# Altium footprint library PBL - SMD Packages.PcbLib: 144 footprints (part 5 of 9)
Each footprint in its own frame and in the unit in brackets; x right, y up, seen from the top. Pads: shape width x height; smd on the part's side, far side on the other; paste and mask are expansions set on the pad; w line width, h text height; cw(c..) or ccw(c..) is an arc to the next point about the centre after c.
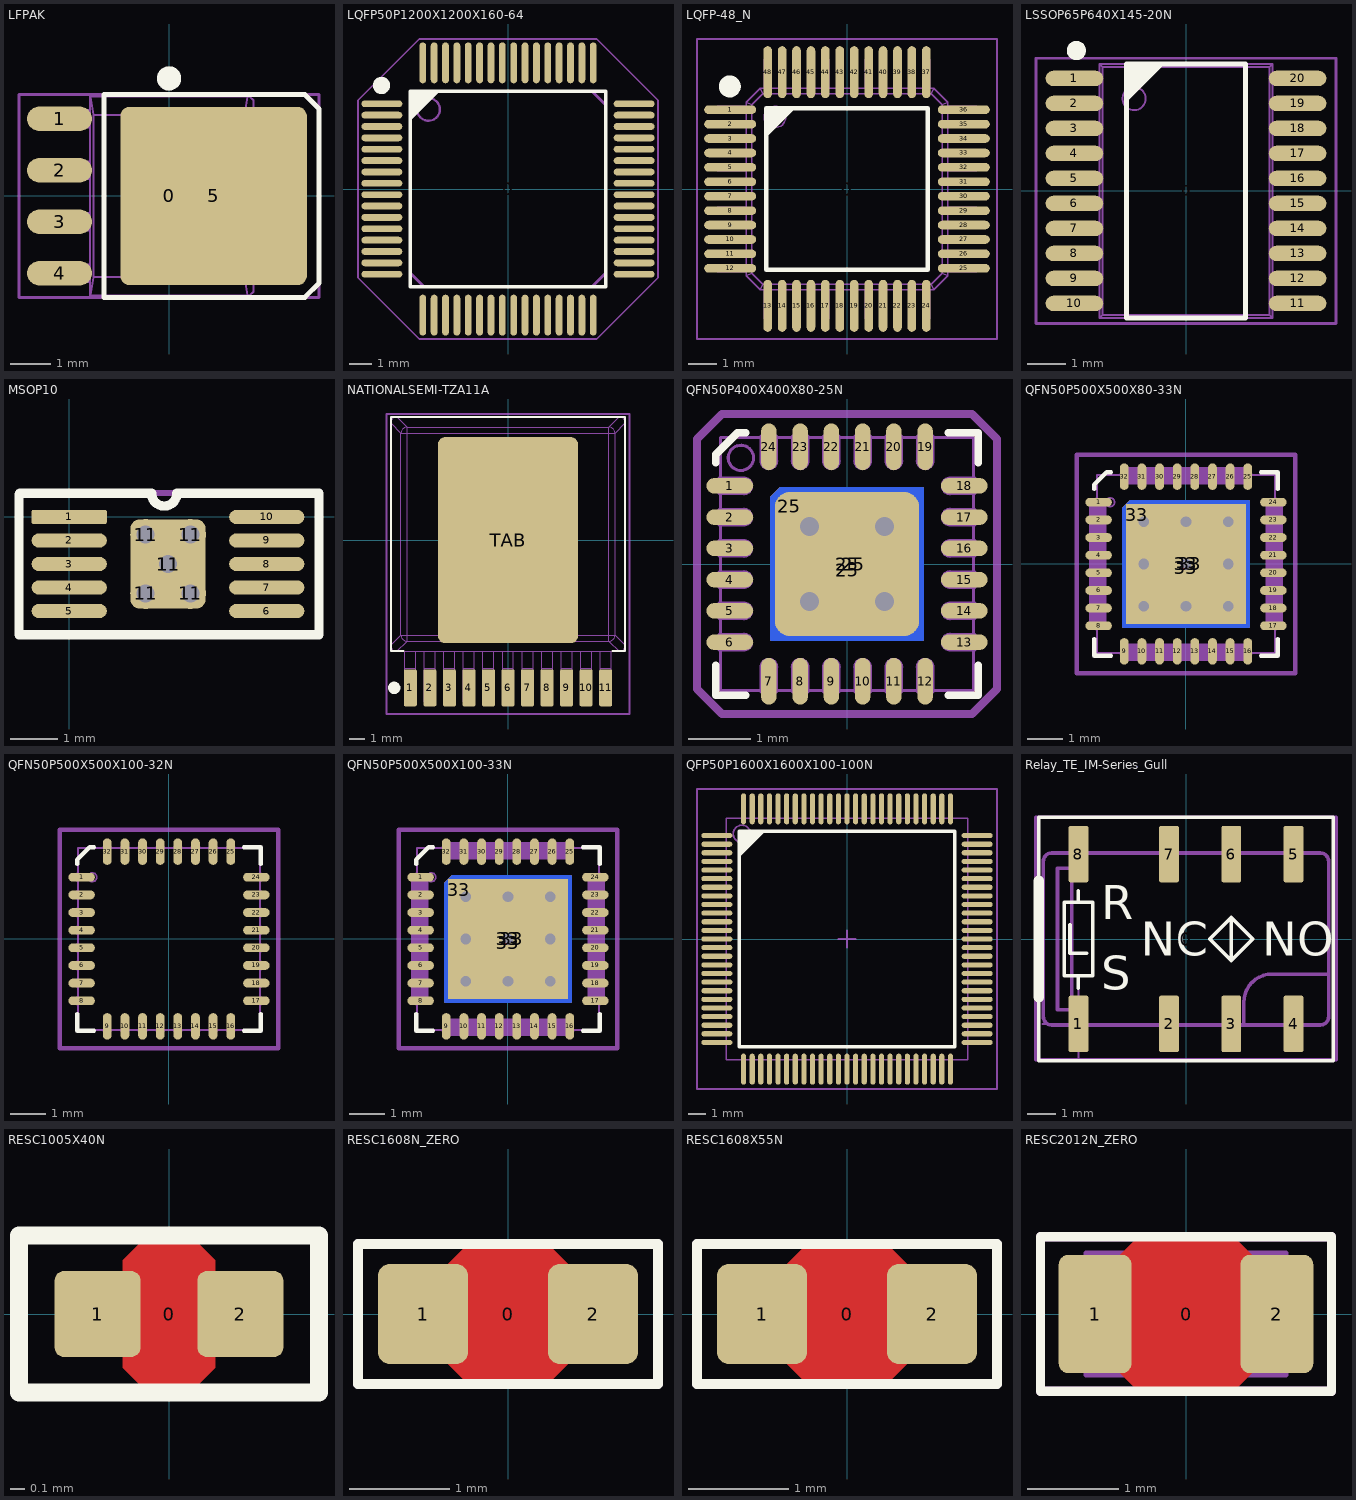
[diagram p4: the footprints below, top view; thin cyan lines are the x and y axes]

## LFPAK [mm] "Renesas LFPAK, a variant of SOIC-8; IPC Medium Density"
height 1.1
pads (6):
  round 1 on Mech15: 0(0,0)
  oval 1.6x0.6 smd: 1(-2.7,1.905) 2(-2.7,0.635) 3(-2.7,-0.635) 4(-2.7,-1.905)
  rrect10% 4.6x4.4 smd paste-0.8: 5(1.1,0)
Top Overlay:
  circle w0.3: c0,2.9 r0.15
  lines w0.127: -1.6,-2.5 -1.6,2.5 3.35,2.5 3.7,2.15 3.7,-2.15 3.35,-2.5 -1.6,-2.5
13 - 3D Top Side:
  circle w0.05: c0,1.5 r0.338
  lines w0.05: -2.631,-2.115 -2.631,-1.695 ; -2.631,-0.845 -2.631,-0.425 ; -2.631,0.425 -2.631,0.845 ; -2.631,1.695 -2.631,2.115 ; -2.543,-2.115 -2.543,-1.695 ; -2.543,-0.845 -2.543,-0.425 ; -2.543,0.425 -2.543,0.845 ; -2.543,1.695 -2.543,2.115 ; -2.506,-2.115 -2.506,-1.695 ; -2.506,-0.845 -2.506,-0.425 ; -2.506,0.425 -2.506,0.845 ; -2.506,1.695 -2.506,2.115 ; -2.217,-2.115 -2.217,-1.695 ; -2.217,-0.845 -2.217,-0.425 ; -2.217,0.425 -2.217,0.845 ; -2.217,1.695 -2.217,2.115 ; -1.95,-2.115 -3,-2.115 -3,-1.695 -1.95,-1.695 ; -1.95,-0.845 -3,-0.845 -3,-0.425 -1.95,-0.425 ; -1.95,0.425 -3,0.425 -3,0.845 -1.95,0.845 ; -1.95,1.695 -3,1.695 -3,2.115 -1.95,2.115 ; -1.937,-2.45 -1.858,-2.003 ; -1.937,2.45 -1.858,2.003 ; 1.937,-2.45 1.858,-2.003 ; 1.937,2.45 1.858,2.003 ; 2.085,-1.4 2.085,-2.358 1.993,-2.45 -1.95,-2.45 -1.95,2.45 1.993,2.45 2.085,2.358 2.085,1.4 ; 2.085,-0.6 2.085,0.6 ; -1.858,-2.003 -1.858,2.003 ; -1.858,-2.003 1.858,-2.003 ; -1.858,2.003 1.858,2.003 ; 1.858,-2.003 1.858,2.003 ; 2.028,-1.4 2.3,-1.4 2.3,-2.1 2.55,-2.1 3,-1.65 3,1.65 2.55,2.1 2.3,2.1 2.3,1.4 2.028,1.4 2.028,0.6 2.1,0.6 2.1,-0.6 2.028,-0.6 2.028,-1.4
15 - Top Courtyards:
  lines w0.076: -3.7,-2.5 -3.7,2.5 3.7,2.5 3.7,-2.5 -3.7,-2.5
3D body "LFPAK.STEP": height 1.1, standoff 0, extent -3,-2.45 3,2.45

## LQFP50P1200X1200X160-64 [mm] "Thin Quad Flat Pack, 64 pins, 0.5mm pitch, 12mm lead span, body 10x10mm, 0.1mm body height, max tolerances, IPC Medium Density"
height 1.6
pads (65):
  round 1 on Mech15: 0(0,0)
  oval 1.8x0.3 smd: 1(-5.55,3.75) 2(-5.55,3.25) 3(-5.55,2.75) 4(-5.55,2.25) 5(-5.55,1.75) 6(-5.55,1.25) 7(-5.55,0.75) 8(-5.55,0.25) 9(-5.55,-0.25) 10(-5.55,-0.75) 11(-5.55,-1.25) 12(-5.55,-1.75) 13(-5.55,-2.25) 14(-5.55,-2.75) 15(-5.55,-3.25) 16(-5.55,-3.75) 33(5.55,-3.75) 34(5.55,-3.25) 35(5.55,-2.75) 36(5.55,-2.25) 37(5.55,-1.75) 38(5.55,-1.25) 39(5.55,-0.75) 40(5.55,-0.25) 41(5.55,0.25) 42(5.55,0.75) 43(5.55,1.25) 44(5.55,1.75) 45(5.55,2.25) 46(5.55,2.75) 47(5.55,3.25) 48(5.55,3.75)
  oval 0.3x1.8 smd: 17(-3.75,-5.55) 18(-3.25,-5.55) 19(-2.75,-5.55) 20(-2.25,-5.55) 21(-1.75,-5.55) 22(-1.25,-5.55) 23(-0.75,-5.55) 24(-0.25,-5.55) 25(0.25,-5.55) 26(0.75,-5.55) 27(1.25,-5.55) 28(1.75,-5.55) 29(2.25,-5.55) 30(2.75,-5.55) 31(3.25,-5.55) 32(3.75,-5.55) 49(3.75,5.55) 50(3.25,5.55) 51(2.75,5.55) 52(2.25,5.55) 53(1.75,5.55) 54(1.25,5.55) 55(0.75,5.55) 56(0.25,5.55) 57(-0.25,5.55) 58(-0.75,5.55) 59(-1.25,5.55) 60(-1.75,5.55) 61(-2.25,5.55) 62(-2.75,5.55) 63(-3.25,5.55) 64(-3.75,5.55)
Top Overlay:
  circle w0.381: c-5.564,4.556 r0.191
  region: -4.294,4.294 -3.006,4.294 -4.294,3.006
  lines w0.152: -4.3,-4.3 4.3,-4.3 4.3,4.3 -4.3,4.3 -4.3,-4.3
13 - 3D Top Side:
  circle w0.1: c-3.5,3.5 r0.5
  lines w0.127: -4.3,-3.7 -3.7,-4.3 3.7,-4.3 4.3,-3.7 4.3,3.7 3.7,4.3 -3.7,4.3 -4.3,3.7 -4.3,-3.7
15 - Top Courtyards:
  lines w0.076: -6.6,-3.9 -3.9,-6.6 3.9,-6.6 6.6,-3.9 6.6,3.9 3.9,6.6 -3.9,6.6 -6.6,3.9 -6.6,-3.9
3D body "LQFP50P1200X1200X160-64.STEP": height 1.59, standoff -0.01, extent -6.1,-6.1 6.1,6.1

## LQFP-48_N [mm] "Thin QFP, 48-Leads, Body 7x7mm, Pitch 0.5mm, IPC Medium Density"
height 1.6
pads (49):
  round 1 on Mech15: 0(0,0)
  oval 1.8x0.3 smd: 1(-4.05,2.75) 2(-4.05,2.25) 3(-4.05,1.75) 4(-4.05,1.25) 5(-4.05,0.75) 6(-4.05,0.25) 7(-4.05,-0.25) 8(-4.05,-0.75) 9(-4.05,-1.25) 10(-4.05,-1.75) 11(-4.05,-2.25) 12(-4.05,-2.75) 25(4.05,-2.75) 26(4.05,-2.25) 27(4.05,-1.75) 28(4.05,-1.25) 29(4.05,-0.75) 30(4.05,-0.25) 31(4.05,0.25) 32(4.05,0.75) 33(4.05,1.25) 34(4.05,1.75) 35(4.05,2.25) 36(4.05,2.75)
  oval 0.3x1.8 smd: 13(-2.75,-4.05) 14(-2.25,-4.05) 15(-1.75,-4.05) 16(-1.25,-4.05) 17(-0.75,-4.05) 18(-0.25,-4.05) 19(0.25,-4.05) 20(0.75,-4.05) 21(1.25,-4.05) 22(1.75,-4.05) 23(2.25,-4.05) 24(2.75,-4.05) 37(2.75,4.05) 38(2.25,4.05) 39(1.75,4.05) 40(1.25,4.05) 41(0.75,4.05) 42(0.25,4.05) 43(-0.25,4.05) 44(-0.75,4.05) 45(-1.25,4.05) 46(-1.75,4.05) 47(-2.25,4.05) 48(-2.75,4.05)
Top Overlay:
  circle w0.381: c-4.064,3.556 r0.191
  region: -2.794,2.794 -1.794,2.794 -2.794,1.794
  lines w0.152: -2.794,-2.794 -2.794,2.794 2.794,2.794 2.794,-2.794 -2.794,-2.794
13 - 3D Top Side:
  drawing of 361 lines, arcs and shapes, not listed
15 - Top Courtyards:
  lines w0.076: -5.2,-5.2 -5.2,5.2 5.2,5.2 5.2,-5.2 -5.2,-5.2
3D body "LQFP-48.STEP": height 1.59, standoff -0.01, extent -4.5,-4.5 4.5,4.5

## LSSOP65P640X145-20N [mm] "LSSOP, 20-Leads, Body 6.6x4.5mm (max), Pitch 0.65mm, IPC Medium Density"
height 1.45
pads (21):
  round 0.508 on Mech15 mask+0.127: 0(0,0)
  oval 1.5x0.4 smd paste-1 mask+0.127: 1(-2.9,2.925) 2(-2.9,2.275) 3(-2.9,1.625) 4(-2.9,0.975) 5(-2.9,0.325) 6(-2.9,-0.325) 7(-2.9,-0.975) 8(-2.9,-1.625) 9(-2.9,-2.275) 10(-2.9,-2.925) 11(2.9,-2.925) 12(2.9,-2.275) 13(2.9,-1.625) 14(2.9,-0.975) 15(2.9,-0.325) 16(2.9,0.325) 17(2.9,0.975) 18(2.9,1.625) 19(2.9,2.275) 20(2.9,2.925)
Top Overlay:
  circle w0.25: c-2.85,3.65 r0.125
  region: -1.55,3.3 -0.55,3.3 -1.55,2.3
  lines w0.127: -1.55,-3.3 -1.55,3.3 1.55,3.3 1.55,-3.3 -1.55,-3.3
Top Paste:
  region: 3.5,-0.825 2.3,-0.825 2.3,-1.125 3.5,-1.125
  region: 3.5,-0.175 2.3,-0.175 2.3,-0.475 3.5,-0.475
  region: 3.5,0.475 2.3,0.475 2.3,0.175 3.5,0.175
  region: 3.5,1.125 2.3,1.125 2.3,0.825 3.5,0.825
  region: 3.5,1.775 2.3,1.775 2.3,1.475 3.5,1.475
  region: 3.5,2.425 2.3,2.425 2.3,2.125 3.5,2.125
  region: 3.5,3.075 2.3,3.075 2.3,2.775 3.5,2.775
  rectangle: -3.5,2.775 -2.3,3.075
  rectangle: -3.5,2.125 -2.3,2.425
  rectangle: -3.5,1.475 -2.3,1.775
  rectangle: -3.5,0.825 -2.3,1.125
  rectangle: -3.5,0.175 -2.3,0.475
  rectangle: -3.5,-0.475 -2.3,-0.175
  rectangle: -3.5,-1.125 -2.3,-0.825
  rectangle: -3.5,-3.075 -2.3,-2.775
  rectangle: -3.5,-2.425 -2.3,-2.125
  rectangle: -3.5,-1.775 -2.3,-1.475
  region: 3.5,-1.475 2.3,-1.475 2.3,-1.775 3.5,-1.775
  region: 3.5,-2.125 2.3,-2.125 2.3,-2.425 3.5,-2.425
  region: 3.5,-2.775 2.3,-2.775 2.3,-3.075 3.5,-3.075
13 - 3D Top Side:
  drawing of 153 lines, arcs and shapes, not listed
15 - Top Courtyards:
  lines w0.076: -3.9,-3.45 -3.9,3.45 3.9,3.45 3.9,-3.45 -3.9,-3.45
3D body "LSSOP65P640X145-20N.STEP": height 1.45, standoff 0, extent -3.3,-3.3 3.3,3.3

## MSOP10 [mm]
pads (16):
  rrect25% 1.6x0.3 smd mask+0.05: 1(0,0)
  oval 1.6x0.3 smd mask+0.05: 2(0,-0.5) 3(0,-1) 4(0,-1.5) 5(0,-2) 6(4.2,-2) 7(4.2,-1.5) 8(4.2,-1) 9(4.2,-0.5) 10(4.2,0)
  round 0.66 hole 0.381: 11(1.625,-1.625) 11(1.625,-0.375) 11(2.1,-1) 11(2.575,-1.625) 11(2.575,-0.375)
  rrect25% 1.6x1.9 smd: 11(2.1,-1)
Top Overlay:
  lines w0.2: 1.725,0.5 -1.049,0.5 -1.067,0.483 -1.067,-2.5 5.309,-2.5 5.309,0.5 2.3,0.5 ; 1.75,0.5 ccw(c2.019,0.5) 2.289,0.5
Top Solder:
  rectangle: 1.175,-2.075 3.025,0.075
15 - Top Courtyards:
  lines w0.127: -1.067,-2.489 -1.067,0.508 5.309,0.508 5.309,-2.489 -1.067,-2.489
3D body: height 0.15, standoff 0, extent -0.375,-2.125 4.6,0.125
3D body: height 1.1, standoff 0, extent 0.625,-2.5 3.625,0.525

## NATIONALSEMI-TZA11A [mm] "National Semi TZA11A package"
height 6
pads (12):
  rrect25% 0.85x2.4 smd: 1(-6.35,-9.6) 2(-5.08,-9.6) 3(-3.81,-9.6) 4(-2.54,-9.6) 5(-1.27,-9.6) 6(0,-9.6) 7(1.27,-9.6) 8(2.54,-9.6) 9(3.81,-9.6) 10(5.08,-9.6) 11(6.35,-9.6)
  rrect10% 9.1x13.4 smd: TAB(0,0)
Top Overlay:
  circle w0.4: c-7.4,-9.6 r0.2
  lines w0.127: -6.8,-7.2 -7.6,-7.2 -7.6,8 7.6,8 7.6,-7.2 6.8,-7.2
13 - 3D Top Side:
  lines w0.05: -6.705,-9.644 -5.995,-9.644 ; -6.705,-9.29 -5.995,-9.29 ; -6.705,-8.865 -5.995,-8.865 ; -6.705,-8.325 -5.995,-8.325 ; -6.705,-7.235 -6.705,-10.515 -5.995,-10.515 -5.995,-7.235 ; -5.435,-9.644 -4.725,-9.644 ; -5.435,-9.29 -4.725,-9.29 ; -5.435,-8.865 -4.725,-8.865 ; -5.435,-8.325 -4.725,-8.325 ; -5.435,-7.235 -5.435,-10.515 -4.725,-10.515 -4.725,-7.235 ; -4.165,-9.644 -3.455,-9.644 ; -4.165,-9.29 -3.455,-9.29 ; -4.165,-8.865 -3.455,-8.865 ; -4.165,-8.325 -3.455,-8.325 ; -4.165,-7.235 -4.165,-10.515 -3.455,-10.515 -3.455,-7.235 ; -2.895,-9.644 -2.185,-9.644 ; -2.895,-9.29 -2.185,-9.29 ; -2.895,-8.865 -2.185,-8.865 ; -2.895,-8.325 -2.185,-8.325 ; -2.895,-7.235 -2.895,-10.515 -2.185,-10.515 -2.185,-7.235 ; -1.625,-9.644 -0.915,-9.644 ; -1.625,-9.29 -0.915,-9.29 ; -1.625,-8.865 -0.915,-8.865 ; -1.625,-8.325 -0.915,-8.325 ; -1.625,-7.235 -1.625,-10.515 -0.915,-10.515 -0.915,-7.235 ; -0.355,-9.644 0.355,-9.644 ; -0.355,-9.29 0.355,-9.29 ; -0.355,-8.865 0.355,-8.865 ; -0.355,-8.325 0.355,-8.325 ; -0.355,-7.235 -0.355,-10.515 0.355,-10.515 0.355,-7.235 ; 0.915,-9.644 1.625,-9.644 ; 0.915,-9.29 1.625,-9.29 ; 0.915,-8.865 1.625,-8.865 ; 0.915,-8.325 1.625,-8.325 ; 0.915,-7.235 0.915,-10.515 1.625,-10.515 1.625,-7.235 ; 2.185,-9.644 2.895,-9.644 ; 2.185,-9.29 2.895,-9.29 ; 2.185,-8.865 2.895,-8.865 ; 2.185,-8.325 2.895,-8.325 ; 2.185,-7.235 2.185,-10.515 2.895,-10.515 2.895,-7.235 ; 3.455,-9.644 4.165,-9.644 ; 3.455,-9.29 4.165,-9.29 ; 3.455,-8.865 4.165,-8.865 ; 3.455,-8.325 4.165,-8.325 ; 3.455,-7.235 3.455,-10.515 4.165,-10.515 4.165,-7.235 ; 4.725,-9.644 5.435,-9.644 ; 4.725,-9.29 5.435,-9.29 ; 4.725,-8.865 5.435,-8.865 ; 4.725,-8.325 5.435,-8.325 ; 4.725,-7.235 4.725,-10.515 5.435,-10.515 5.435,-7.235 ; 5.995,-9.644 6.705,-9.644 ; 5.995,-9.29 6.705,-9.29 ; 5.995,-8.865 6.705,-8.865 ; 5.995,-8.325 6.705,-8.325 ; 5.995,-7.235 5.995,-10.515 6.705,-10.515 6.705,-7.235 ; -7.625,-6.839 ccw(c-7.225,-6.835) -7.229,-7.235 ; -7.625,-6.839 -7.625,-6.835 -7.625,7.615 -7.625,7.619 ; -7.625,-6.839 -6.958,-6.172 ; -7.625,7.619 cw(c-7.225,7.615) -7.229,8.015 ; -7.625,7.619 -6.958,6.952 ; -7.229,-7.235 -7.225,-7.235 7.225,-7.235 7.229,-7.235 ; -7.229,-7.235 -6.562,-6.568 ; -7.229,8.015 -7.225,8.015 7.225,8.015 7.229,8.015 ; -7.229,8.015 -6.562,7.348 ; -6.958,-6.172 ccw(c-6.553,-6.163) -6.562,-6.568 ; -6.958,-6.172 -6.958,6.952 ; -6.958,-6.172 6.958,-6.172 ; -6.958,6.952 cw(c-6.553,6.943) -6.562,7.348 ; -6.958,6.952 6.958,6.952 ; -6.562,-6.568 -6.562,7.348 ; -6.562,-6.568 6.562,-6.568 ; -6.562,7.348 6.562,7.348 ; 6.562,-6.568 ccw(c6.553,-6.163) 6.958,-6.172 ; 6.562,-6.568 7.229,-7.235 ; 6.562,-6.568 6.562,7.348 ; 6.562,7.348 cw(c6.553,6.943) 6.958,6.952 ; 6.562,7.348 7.229,8.015 ; 6.958,-6.172 7.625,-6.839 ; 6.958,-6.172 6.958,6.952 ; 6.958,6.952 7.625,7.619 ; 7.229,-7.235 ccw(c7.225,-6.835) 7.625,-6.839 ; 7.229,8.015 cw(c7.225,7.615) 7.625,7.619 ; 7.625,-6.839 7.625,-6.835 7.625,7.615 7.625,7.619
15 - Top Courtyards:
  lines w0.127: -7.9,-11.3 -7.9,8.2 7.9,8.2 7.9,-11.3 -7.9,-11.3
3D body "NATIONALSEMI-TZA11A.STEP": height 6, standoff 0, extent -7.625,-10.515 7.625,8.015

## QFN50P400X400X80-25N [mm] "QFN, 24-Leads with exposed die pad, Body 4.05x4.05mm (max), Pitch 0.50mm, IPC Medium Density"
height 0.8
pads (28):
  oval 0.75x0.25 smd mask+0.075: 1(-1.875,1.25) 2(-1.875,0.75) 3(-1.875,0.25) 4(-1.875,-0.25) 5(-1.875,-0.75) 6(-1.875,-1.25) 13(1.875,-1.25) 14(1.875,-0.75) 15(1.875,-0.25) 16(1.875,0.25) 17(1.875,0.75) 18(1.875,1.25)
  oval 0.25x0.75 smd mask+0.075: 7(-1.25,-1.875) 8(-0.75,-1.875) 9(-0.25,-1.875) 10(0.25,-1.875) 11(0.75,-1.875) 12(1.25,-1.875) 19(1.25,1.875) 20(0.75,1.875) 21(0.25,1.875) 22(-0.25,1.875) 23(-0.75,1.875) 24(-1.25,1.875)
  oct 0.6x0.6 smd far side paste-1.7: 25(-0.925,0.925)
  rrect1% 2.45x2.25 smd far side paste-1.7: 25(0,-0.1)
  rrect20% 2.3x2.3 smd paste-1.7: 25(0,0)
  rrect1% 2.25x2.45 smd far side paste-1.7: 25(0.1,0)
via -0.6,-0.6 diameter 0.4 hole 0.3
via 0.6,-0.6 diameter 0.4 hole 0.3
via 0.6,0.6 diameter 0.4 hole 0.3
via -0.6,0.6 diameter 0.4 hole 0.3
Top Layer:
  region: 1.025,-1.225 1.225,-1.225 1.225,1.225 1.025,1.225
  region: 1.225,-1.225 1.225,-1.025 -1.225,-1.025 -1.225,-1.225
  region: -1.225,1.075 -1.075,1.225 1.225,1.225 1.225,1.075
  region: -1.075,1.225 -1.225,1.075 -1.225,-1.225 -1.075,-1.225
Top Overlay:
  lines w0.127: -2.1,-1.625 -2.1,-2.1 -1.625,-2.1 ; -2.1,1.625 -2.1,1.75 -1.75,2.1 -1.625,2.1 ; 1.625,-2.1 2.1,-2.1 2.1,-1.625 ; 1.625,2.1 2.1,2.1 2.1,1.625
  text "." at -2.63,1.25 h0.05
Top Paste:
  region: -1.1,-0.3 -1.1,0.3 -1,0.4 -0.5,0.4 -0.4,0.5 -0.4,1 -0.3,1.1 0.3,1.1 0.4,1 0.4,0.5 0.5,0.4 1,0.4 1.1,0.3 1.1,-0.3 1,-0.4 0.5,-0.4 0.4,-0.5 0.4,-1 0.3,-1.1 -0.3,-1.1 -0.4,-1 -0.4,-0.5 -0.5,-0.4 -1,-0.4
Bottom Paste:
  region: 0.2,1 -0.2,1 -0.4,0.8 -0.4,0.5 -0.5,0.4 -0.8,0.4 -1,0.2 -1,-0.2 -0.8,-0.4 -0.5,-0.4 -0.4,-0.5 -0.4,-0.8 -0.2,-1 0.2,-1 0.4,-0.8 0.4,-0.5 0.5,-0.4 0.8,-0.4 1,-0.2 1,0.2 0.8,0.4 0.5,0.4 0.4,0.5 0.4,0.8
Top Solder:
  circle w0.4: c-0.6,-0.6 r0.4
  circle w0.4: c0.6,-0.6 r0.4
  circle w0.4: c0.6,0.6 r0.4
  circle w0.4: c-0.6,0.6 r0.4
  rectangle: -0.3,-1.225 0.3,1.2
  region: 1.225,-0.3 1.225,0.3 -1.2,0.3 -1.2,-0.3
13 - 3D Top Side:
  circle w0.05: c-1.698,1.698 r0.202
  lines w0.05: -2.025,-1.375 -2.025,-2.025 -1.375,-2.025 ; -2.025,-1.125 -2.025,-0.875 ; -2.025,-0.625 -2.025,-0.375 ; -2.025,-0.125 -2.025,0.125 ; -2.025,0.375 -2.025,0.625 ; -2.025,0.875 -2.025,1.125 ; -2.025,1.375 -2.025,2.025 -1.375,2.025 ; -1.125,-2.025 -0.875,-2.025 ; -1.125,2.025 -0.875,2.025 ; -0.625,-2.025 -0.375,-2.025 ; -0.625,2.025 -0.375,2.025 ; -0.125,-2.025 0.125,-2.025 ; -0.125,2.025 0.125,2.025 ; 0.375,-2.025 0.625,-2.025 ; 0.375,2.025 0.625,2.025 ; 0.875,-2.025 1.125,-2.025 ; 0.875,2.025 1.125,2.025 ; 1.375,-2.025 2.025,-2.025 2.025,-1.375 ; 1.375,2.025 2.025,2.025 2.025,1.375 ; 2.025,-1.125 2.025,-0.875 ; 2.025,-0.625 2.025,-0.375 ; 2.025,-0.125 2.025,0.125 ; 2.025,0.375 2.025,0.625 ; 2.025,0.875 2.025,1.125 ; -2.045,-1.375 -1.65,-1.375 ccw(c-1.65,-1.25) -1.65,-1.125 -2.045,-1.125 -2.045,-1.375 ; -2.045,-0.875 -1.65,-0.875 ccw(c-1.65,-0.75) -1.65,-0.625 -2.045,-0.625 -2.045,-0.875 ; -2.045,-0.375 -1.65,-0.375 ccw(c-1.65,-0.25) -1.65,-0.125 -2.045,-0.125 -2.045,-0.375 ; -2.045,0.125 -1.65,0.125 ccw(c-1.65,0.25) -1.65,0.375 -2.045,0.375 -2.045,0.125 ; -2.045,0.625 -1.65,0.625 ccw(c-1.65,0.75) -1.65,0.875 -2.045,0.875 -2.045,0.625 ; -2.045,1.125 -1.65,1.125 ccw(c-1.65,1.25) -1.65,1.375 -2.045,1.375 -2.045,1.125 ; -1.375,-2.045 -1.375,-1.65 cw(c-1.25,-1.65) -1.125,-1.65 -1.125,-2.045 -1.375,-2.045 ; -1.375,1.65 ccw(c-1.25,1.65) -1.125,1.65 -1.125,2.045 -1.375,2.045 -1.375,1.65 ; -0.875,-2.045 -0.875,-1.65 cw(c-0.75,-1.65) -0.625,-1.65 -0.625,-2.045 -0.875,-2.045 ; -0.875,1.65 ccw(c-0.75,1.65) -0.625,1.65 -0.625,2.045 -0.875,2.045 -0.875,1.65 ; -0.375,-2.045 -0.375,-1.65 cw(c-0.25,-1.65) -0.125,-1.65 -0.125,-2.045 -0.375,-2.045 ; -0.375,1.65 ccw(c-0.25,1.65) -0.125,1.65 -0.125,2.045 -0.375,2.045 -0.375,1.65 ; 0.125,-2.045 0.125,-1.65 cw(c0.25,-1.65) 0.375,-1.65 0.375,-2.045 0.125,-2.045 ; 0.125,1.65 ccw(c0.25,1.65) 0.375,1.65 0.375,2.045 0.125,2.045 0.125,1.65 ; 0.625,-2.045 0.625,-1.65 cw(c0.75,-1.65) 0.875,-1.65 0.875,-2.045 0.625,-2.045 ; 0.625,1.65 ccw(c0.75,1.65) 0.875,1.65 0.875,2.045 0.625,2.045 0.625,1.65 ; 1.125,-2.045 1.125,-1.65 cw(c1.25,-1.65) 1.375,-1.65 1.375,-2.045 1.125,-2.045 ; 1.125,1.65 ccw(c1.25,1.65) 1.375,1.65 1.375,2.045 1.125,2.045 1.125,1.65 ; 1.65,-1.375 cw(c1.65,-1.25) 1.65,-1.125 2.045,-1.125 2.045,-1.375 1.65,-1.375 ; 1.65,-0.875 cw(c1.65,-0.75) 1.65,-0.625 2.045,-0.625 2.045,-0.875 1.65,-0.875 ; 1.65,-0.375 cw(c1.65,-0.25) 1.65,-0.125 2.045,-0.125 2.045,-0.375 1.65,-0.375 ; 1.65,0.125 cw(c1.65,0.25) 1.65,0.375 2.045,0.375 2.045,0.125 1.65,0.125 ; 1.65,0.625 cw(c1.65,0.75) 1.65,0.875 2.045,0.875 2.045,0.625 1.65,0.625 ; 1.65,1.125 cw(c1.65,1.25) 1.65,1.375 2.045,1.375 2.045,1.125 1.65,1.125
15 - Top Courtyards:
  lines w0.127: -2.4,-2 -2.4,2 -2,2.4 2,2.4 2.4,2 2.4,-2 2,-2.4 -2,-2.4 -2.4,-2
3D body "QFN50P400X400X80-25N.STEP": height 0.8, standoff 0, extent -2.045,-2.045 2.045,2.045

## QFN50P500X500X80-33N [mm] "QFN, 32-Leads with exposed die pad, Body 5.1x5.1mm (max), Pitch 0.50mm, IPC Medium Density"
height 0.8
pads (36):
  oval 0.75x0.25 smd mask+0.075: 1(-2.475,1.75) 2(-2.475,1.25) 3(-2.475,0.75) 4(-2.475,0.25) 5(-2.475,-0.25) 6(-2.475,-0.75) 7(-2.475,-1.25) 8(-2.475,-1.75) 17(2.475,-1.75) 18(2.475,-1.25) 19(2.475,-0.75) 20(2.475,-0.25) 21(2.475,0.25) 22(2.475,0.75) 23(2.475,1.25) 24(2.475,1.75)
  oval 0.25x0.75 smd mask+0.075: 9(-1.75,-2.475) 10(-1.25,-2.475) 11(-0.75,-2.475) 12(-0.25,-2.475) 13(0.25,-2.475) 14(0.75,-2.475) 15(1.25,-2.475) 16(1.75,-2.475) 25(1.75,2.475) 26(1.25,2.475) 27(0.75,2.475) 28(0.25,2.475) 29(-0.25,2.475) 30(-0.75,2.475) 31(-1.25,2.475) 32(-1.75,2.475)
  oct 0.8x0.8 smd far side paste-1.7: 33(-1.4,1.4)
  rrect1% 3.6x3.4 smd far side paste-1.7: 33(0,-0.1)
  rect 3.4x3.4 smd paste-1.7: 33(0,0)
  rrect1% 3.4x3.6 smd far side paste-1.7: 33(0.1,0)
via 0,0 diameter 0.4 hole 0.3
via 0,-1.2 diameter 0.4 hole 0.3
via 1.2,0 diameter 0.4 hole 0.3
via 0,1.2 diameter 0.4 hole 0.3
via -1.2,0 diameter 0.4 hole 0.3
via -1.2,-1.2 diameter 0.4 hole 0.3
via 1.2,-1.2 diameter 0.4 hole 0.3
via 1.2,1.2 diameter 0.4 hole 0.3
via -1.2,1.2 diameter 0.4 hole 0.3
Top Layer:
  region: -1.8,1.6 -1.6,1.8 1.8,1.8 1.8,1.6
  region: -1.6,1.8 -1.8,1.6 -1.8,-1.8 -1.6,-1.8
  region: -1.8,-1.6 -1.6,-1.8 1.8,-1.8 1.8,-1.6
  region: 1.6,-1.8 1.8,-1.6 1.8,1.8 1.6,1.8
Top Overlay:
  lines w0.127: -2.6,-2.125 -2.6,-2.6 -2.125,-2.6 ; -2.6,2.125 -2.6,2.25 -2.25,2.6 -2.125,2.6 ; 2.125,-2.6 2.6,-2.6 2.6,-2.125 ; 2.125,2.6 2.6,2.6 2.6,2.125
  text "." at -3.23,1.75 h0.05
Top Paste:
  region: -1.8,0.9 -1.7,1 -1.1,1 -1,1.1 -1,1.7 -0.9,1.8 -0.3,1.8 -0.2,1.7 -0.2,0.3 -0.3,0.2 -1.7,0.2 -1.8,0.3
  region: -0.9,-1.8 -1,-1.7 -1,-1.1 -1.1,-1 -1.7,-1 -1.8,-0.9 -1.8,-0.3 -1.7,-0.2 -0.3,-0.2 -0.2,-0.3 -0.2,-1.7 -0.3,-1.8
  region: 1.8,-0.9 1.7,-1 1.1,-1 1,-1.1 1,-1.7 0.9,-1.8 0.3,-1.8 0.2,-1.7 0.2,-0.3 0.3,-0.2 1.7,-0.2 1.8,-0.3
  region: 0.9,1.8 1,1.7 1,1.1 1.1,1 1.7,1 1.8,0.9 1.8,0.3 1.7,0.2 0.3,0.2 0.2,0.3 0.2,1.7 0.3,1.8
Top Solder:
  circle w0.4: c0,-1.2 r0.4
  circle w0.4: c1.2,0 r0.4
  circle w0.4: c0,1.2 r0.4
  circle w0.4: c-1.2,0 r0.4
  circle w0.4: c-1.2,1.2 r0.4
  circle w0.4: c1.2,1.2 r0.4
  circle w0.4: c1.2,-1.2 r0.4
  circle w0.4: c0,0 r0.4
  circle w0.4: c-1.2,-1.2 r0.4
  rectangle: -0.9,-1.8 -0.3,1.8
  region: 0.9,1.8 0.3,1.8 0.3,-1.8 0.9,-1.8
  region: -1.8,0.9 -1.8,0.3 1.8,0.3 1.8,0.9
  region: 1.8,-0.9 1.8,-0.3 -1.8,-0.3 -1.8,-0.9
Mechanical 3:
  region: 2.25,1.75 2.25,-1.75 2.75,-1.75 2.75,1.75
  region: 1.75,-2.25 -1.75,-2.25 -1.75,-2.75 1.75,-2.75
  region: -2.25,-1.75 -2.25,1.75 -2.75,1.75 -2.75,-1.75
  rectangle: -1.75,2.25 1.75,2.75
13 - 3D Top Side:
  circle w0.05: c-2.148,1.75 r0.125
  lines w0.05: -2.525,-1.875 -2.545,-1.875 -2.545,-1.625 -2.525,-1.625 ; -2.525,-1.375 -2.545,-1.375 -2.545,-1.125 -2.525,-1.125 ; -2.525,-0.875 -2.545,-0.875 -2.545,-0.625 -2.525,-0.625 ; -2.525,-0.375 -2.545,-0.375 -2.545,-0.125 -2.525,-0.125 ; -2.525,0.125 -2.545,0.125 -2.545,0.375 -2.525,0.375 ; -2.525,0.625 -2.545,0.625 -2.545,0.875 -2.525,0.875 ; -2.525,1.125 -2.545,1.125 -2.545,1.375 -2.525,1.375 ; -2.525,1.625 -2.545,1.625 -2.545,1.875 -2.525,1.875 ; -1.875,-2.525 -1.875,-2.545 -1.625,-2.545 -1.625,-2.525 ; -1.875,2.525 -1.875,2.545 -1.625,2.545 -1.625,2.525 ; -1.375,-2.525 -1.375,-2.545 -1.125,-2.545 -1.125,-2.525 ; -1.375,2.525 -1.375,2.545 -1.125,2.545 -1.125,2.525 ; -0.875,-2.525 -0.875,-2.545 -0.625,-2.545 -0.625,-2.525 ; -0.875,2.525 -0.875,2.545 -0.625,2.545 -0.625,2.525 ; -0.375,-2.525 -0.375,-2.545 -0.125,-2.545 -0.125,-2.525 ; -0.375,2.525 -0.375,2.545 -0.125,2.545 -0.125,2.525 ; 0.125,-2.525 0.125,-2.545 0.375,-2.545 0.375,-2.525 ; 0.125,2.525 0.125,2.545 0.375,2.545 0.375,2.525 ; 0.625,-2.525 0.625,-2.545 0.875,-2.545 0.875,-2.525 ; 0.625,2.525 0.625,2.545 0.875,2.545 0.875,2.525 ; 1.125,-2.525 1.125,-2.545 1.375,-2.545 1.375,-2.525 ; 1.125,2.525 1.125,2.545 1.375,2.545 1.375,2.525 ; 1.625,-2.525 1.625,-2.545 1.875,-2.545 1.875,-2.525 ; 1.625,2.525 1.625,2.545 1.875,2.545 1.875,2.525 ; 2.525,-1.875 2.545,-1.875 2.545,-1.625 2.525,-1.625 ; 2.525,-1.375 2.545,-1.375 2.545,-1.125 2.525,-1.125 ; 2.525,-0.875 2.545,-0.875 2.545,-0.625 2.525,-0.625 ; 2.525,-0.375 2.545,-0.375 2.545,-0.125 2.525,-0.125 ; 2.525,0.125 2.545,0.125 2.545,0.375 2.525,0.375 ; 2.525,0.625 2.545,0.625 2.545,0.875 2.525,0.875 ; 2.525,1.125 2.545,1.125 2.545,1.375 2.525,1.375 ; 2.525,1.625 2.545,1.625 2.545,1.875 2.525,1.875 ; -2.525,-2.525 2.525,-2.525 2.525,2.525 -2.525,2.525 -2.525,-2.525
15 - Top Courtyards:
  lines w0.127: -3.1,-3.1 -3.1,3.1 3.1,3.1 3.1,-3.1 -3.1,-3.1
3D body "QFN50P500X500X80-33N.STEP": height 0.8, standoff 0, extent -2.545,-2.545 2.545,2.545

## QFN50P500X500X100-32N [mm] "QFN, 32-Leads, Body 5.2x5.2mm (max), Pitch 0.50mm, IPC Medium Density"
height 1
pads (32):
  oval 0.75x0.25 smd: 1(-2.475,1.75) 2(-2.475,1.25) 3(-2.475,0.75) 4(-2.475,0.25) 5(-2.475,-0.25) 6(-2.475,-0.75) 7(-2.475,-1.25) 8(-2.475,-1.75) 17(2.475,-1.75) 18(2.475,-1.25) 19(2.475,-0.75) 20(2.475,-0.25) 21(2.475,0.25) 22(2.475,0.75) 23(2.475,1.25) 24(2.475,1.75)
  oval 0.25x0.75 smd: 9(-1.75,-2.475) 10(-1.25,-2.475) 11(-0.75,-2.475) 12(-0.25,-2.475) 13(0.25,-2.475) 14(0.75,-2.475) 15(1.25,-2.475) 16(1.75,-2.475) 25(1.75,2.475) 26(1.25,2.475) 27(0.75,2.475) 28(0.25,2.475) 29(-0.25,2.475) 30(-0.75,2.475) 31(-1.25,2.475) 32(-1.75,2.475)
Top Overlay:
  lines w0.127: -2.6,-2.125 -2.6,-2.6 -2.125,-2.6 ; -2.6,2.125 -2.6,2.25 -2.25,2.6 -2.125,2.6 ; 2.125,-2.6 2.6,-2.6 2.6,-2.125 ; 2.125,2.6 2.6,2.6 2.6,2.125
  text "." at -3.23,1.75 h0.05
Top Solder:
  region: 2.25,1.75 2.25,-1.75 2.75,-1.75 2.75,1.75
  region: 1.75,-2.25 -1.75,-2.25 -1.75,-2.75 1.75,-2.75
  region: -2.25,-1.75 -2.25,1.75 -2.75,1.75 -2.75,-1.75
  rectangle: -1.75,2.25 1.75,2.75
13 - 3D Top Side:
  circle w0.05: c-2.173,1.75 r0.125
  lines w0.05: -2.575,-1.875 -2.595,-1.875 -2.595,-1.625 -2.575,-1.625 ; -2.575,-1.375 -2.595,-1.375 -2.595,-1.125 -2.575,-1.125 ; -2.575,-0.875 -2.595,-0.875 -2.595,-0.625 -2.575,-0.625 ; -2.575,-0.375 -2.595,-0.375 -2.595,-0.125 -2.575,-0.125 ; -2.575,0.125 -2.595,0.125 -2.595,0.375 -2.575,0.375 ; -2.575,0.625 -2.595,0.625 -2.595,0.875 -2.575,0.875 ; -2.575,1.125 -2.595,1.125 -2.595,1.375 -2.575,1.375 ; -2.575,1.625 -2.595,1.625 -2.595,1.875 -2.575,1.875 ; -1.875,-2.575 -1.875,-2.595 -1.625,-2.595 -1.625,-2.575 ; -1.875,2.575 -1.875,2.595 -1.625,2.595 -1.625,2.575 ; -1.375,-2.575 -1.375,-2.595 -1.125,-2.595 -1.125,-2.575 ; -1.375,2.575 -1.375,2.595 -1.125,2.595 -1.125,2.575 ; -0.875,-2.575 -0.875,-2.595 -0.625,-2.595 -0.625,-2.575 ; -0.875,2.575 -0.875,2.595 -0.625,2.595 -0.625,2.575 ; -0.375,-2.575 -0.375,-2.595 -0.125,-2.595 -0.125,-2.575 ; -0.375,2.575 -0.375,2.595 -0.125,2.595 -0.125,2.575 ; 0.125,-2.575 0.125,-2.595 0.375,-2.595 0.375,-2.575 ; 0.125,2.575 0.125,2.595 0.375,2.595 0.375,2.575 ; 0.625,-2.575 0.625,-2.595 0.875,-2.595 0.875,-2.575 ; 0.625,2.575 0.625,2.595 0.875,2.595 0.875,2.575 ; 1.125,-2.575 1.125,-2.595 1.375,-2.595 1.375,-2.575 ; 1.125,2.575 1.125,2.595 1.375,2.595 1.375,2.575 ; 1.625,-2.575 1.625,-2.595 1.875,-2.595 1.875,-2.575 ; 1.625,2.575 1.625,2.595 1.875,2.595 1.875,2.575 ; 2.575,-1.875 2.595,-1.875 2.595,-1.625 2.575,-1.625 ; 2.575,-1.375 2.595,-1.375 2.595,-1.125 2.575,-1.125 ; 2.575,-0.875 2.595,-0.875 2.595,-0.625 2.575,-0.625 ; 2.575,-0.375 2.595,-0.375 2.595,-0.125 2.575,-0.125 ; 2.575,0.125 2.595,0.125 2.595,0.375 2.575,0.375 ; 2.575,0.625 2.595,0.625 2.595,0.875 2.575,0.875 ; 2.575,1.125 2.595,1.125 2.595,1.375 2.575,1.375 ; 2.575,1.625 2.595,1.625 2.595,1.875 2.575,1.875 ; -2.575,-2.575 2.575,-2.575 2.575,2.575 -2.575,2.575 -2.575,-2.575
15 - Top Courtyards:
  lines w0.127: -3.1,-3.1 -3.1,3.1 3.1,3.1 3.1,-3.1 -3.1,-3.1
3D body "QFN50P500X500X100-32N.STEP": height 1, standoff 0, extent -2.595,-2.595 2.595,2.595

## QFN50P500X500X100-33N [mm] "QFN, 32-Leads with exposed die pad, Body 5.2x5.2mm (max), Pitch 0.50mm, IPC Medium Density"
height 1
pads (36):
  oval 0.75x0.25 smd mask+0.075: 1(-2.475,1.75) 2(-2.475,1.25) 3(-2.475,0.75) 4(-2.475,0.25) 5(-2.475,-0.25) 6(-2.475,-0.75) 7(-2.475,-1.25) 8(-2.475,-1.75) 17(2.475,-1.75) 18(2.475,-1.25) 19(2.475,-0.75) 20(2.475,-0.25) 21(2.475,0.25) 22(2.475,0.75) 23(2.475,1.25) 24(2.475,1.75)
  oval 0.25x0.75 smd mask+0.075: 9(-1.75,-2.475) 10(-1.25,-2.475) 11(-0.75,-2.475) 12(-0.25,-2.475) 13(0.25,-2.475) 14(0.75,-2.475) 15(1.25,-2.475) 16(1.75,-2.475) 25(1.75,2.475) 26(1.25,2.475) 27(0.75,2.475) 28(0.25,2.475) 29(-0.25,2.475) 30(-0.75,2.475) 31(-1.25,2.475) 32(-1.75,2.475)
  oct 0.8x0.8 smd far side paste-1.7: 33(-1.4,1.4)
  rrect1% 3.6x3.4 smd far side paste-1.7: 33(0,-0.1)
  rect 3.4x3.4 smd paste-1.7: 33(0,0)
  rrect1% 3.4x3.6 smd far side paste-1.7: 33(0.1,0)
via -1.2,1.2 diameter 0.4 hole 0.3
via 1.2,1.2 diameter 0.4 hole 0.3
via 1.2,-1.2 diameter 0.4 hole 0.3
via -1.2,-1.2 diameter 0.4 hole 0.3
via -1.2,0 diameter 0.4 hole 0.3
via 0,1.2 diameter 0.4 hole 0.3
via 1.2,0 diameter 0.4 hole 0.3
via 0,-1.2 diameter 0.4 hole 0.3
via 0,0 diameter 0.4 hole 0.3
Top Layer:
  region: 1.6,-1.8 1.8,-1.6 1.8,1.8 1.6,1.8
  region: -1.8,-1.6 -1.6,-1.8 1.8,-1.8 1.8,-1.6
  region: -1.6,1.8 -1.8,1.6 -1.8,-1.8 -1.6,-1.8
  region: -1.8,1.6 -1.6,1.8 1.8,1.8 1.8,1.6
Top Overlay:
  lines w0.127: -2.6,-2.125 -2.6,-2.6 -2.125,-2.6 ; -2.6,2.125 -2.6,2.25 -2.25,2.6 -2.125,2.6 ; 2.125,-2.6 2.6,-2.6 2.6,-2.125 ; 2.125,2.6 2.6,2.6 2.6,2.125
  text "." at -3.23,1.75 h0.05
Top Paste:
  region: 0.9,1.8 1,1.7 1,1.1 1.1,1 1.7,1 1.8,0.9 1.8,0.3 1.7,0.2 0.3,0.2 0.2,0.3 0.2,1.7 0.3,1.8
  region: 1.8,-0.9 1.7,-1 1.1,-1 1,-1.1 1,-1.7 0.9,-1.8 0.3,-1.8 0.2,-1.7 0.2,-0.3 0.3,-0.2 1.7,-0.2 1.8,-0.3
  region: -0.9,-1.8 -1,-1.7 -1,-1.1 -1.1,-1 -1.7,-1 -1.8,-0.9 -1.8,-0.3 -1.7,-0.2 -0.3,-0.2 -0.2,-0.3 -0.2,-1.7 -0.3,-1.8
  region: -1.8,0.9 -1.7,1 -1.1,1 -1,1.1 -1,1.7 -0.9,1.8 -0.3,1.8 -0.2,1.7 -0.2,0.3 -0.3,0.2 -1.7,0.2 -1.8,0.3
Top Solder:
  circle w0.4: c-1.2,-1.2 r0.4
  circle w0.4: c0,0 r0.4
  circle w0.4: c1.2,-1.2 r0.4
  circle w0.4: c1.2,1.2 r0.4
  circle w0.4: c-1.2,1.2 r0.4
  circle w0.4: c-1.2,0 r0.4
  circle w0.4: c0,1.2 r0.4
  circle w0.4: c1.2,0 r0.4
  circle w0.4: c0,-1.2 r0.4
  region: 1.8,-0.9 1.8,-0.3 -1.8,-0.3 -1.8,-0.9
  region: -1.8,0.9 -1.8,0.3 1.8,0.3 1.8,0.9
  region: 0.9,1.8 0.3,1.8 0.3,-1.8 0.9,-1.8
  rectangle: -0.9,-1.8 -0.3,1.8
Mechanical 3:
  region: 2.25,1.75 2.25,-1.75 2.75,-1.75 2.75,1.75
  region: 1.75,-2.25 -1.75,-2.25 -1.75,-2.75 1.75,-2.75
  region: -2.25,-1.75 -2.25,1.75 -2.75,1.75 -2.75,-1.75
  rectangle: -1.75,2.25 1.75,2.75
13 - 3D Top Side:
  circle w0.05: c-2.173,1.75 r0.125
  lines w0.05: -2.575,-1.875 -2.595,-1.875 -2.595,-1.625 -2.575,-1.625 ; -2.575,-1.375 -2.595,-1.375 -2.595,-1.125 -2.575,-1.125 ; -2.575,-0.875 -2.595,-0.875 -2.595,-0.625 -2.575,-0.625 ; -2.575,-0.375 -2.595,-0.375 -2.595,-0.125 -2.575,-0.125 ; -2.575,0.125 -2.595,0.125 -2.595,0.375 -2.575,0.375 ; -2.575,0.625 -2.595,0.625 -2.595,0.875 -2.575,0.875 ; -2.575,1.125 -2.595,1.125 -2.595,1.375 -2.575,1.375 ; -2.575,1.625 -2.595,1.625 -2.595,1.875 -2.575,1.875 ; -1.875,-2.575 -1.875,-2.595 -1.625,-2.595 -1.625,-2.575 ; -1.875,2.575 -1.875,2.595 -1.625,2.595 -1.625,2.575 ; -1.375,-2.575 -1.375,-2.595 -1.125,-2.595 -1.125,-2.575 ; -1.375,2.575 -1.375,2.595 -1.125,2.595 -1.125,2.575 ; -0.875,-2.575 -0.875,-2.595 -0.625,-2.595 -0.625,-2.575 ; -0.875,2.575 -0.875,2.595 -0.625,2.595 -0.625,2.575 ; -0.375,-2.575 -0.375,-2.595 -0.125,-2.595 -0.125,-2.575 ; -0.375,2.575 -0.375,2.595 -0.125,2.595 -0.125,2.575 ; 0.125,-2.575 0.125,-2.595 0.375,-2.595 0.375,-2.575 ; 0.125,2.575 0.125,2.595 0.375,2.595 0.375,2.575 ; 0.625,-2.575 0.625,-2.595 0.875,-2.595 0.875,-2.575 ; 0.625,2.575 0.625,2.595 0.875,2.595 0.875,2.575 ; 1.125,-2.575 1.125,-2.595 1.375,-2.595 1.375,-2.575 ; 1.125,2.575 1.125,2.595 1.375,2.595 1.375,2.575 ; 1.625,-2.575 1.625,-2.595 1.875,-2.595 1.875,-2.575 ; 1.625,2.575 1.625,2.595 1.875,2.595 1.875,2.575 ; 2.575,-1.875 2.595,-1.875 2.595,-1.625 2.575,-1.625 ; 2.575,-1.375 2.595,-1.375 2.595,-1.125 2.575,-1.125 ; 2.575,-0.875 2.595,-0.875 2.595,-0.625 2.575,-0.625 ; 2.575,-0.375 2.595,-0.375 2.595,-0.125 2.575,-0.125 ; 2.575,0.125 2.595,0.125 2.595,0.375 2.575,0.375 ; 2.575,0.625 2.595,0.625 2.595,0.875 2.575,0.875 ; 2.575,1.125 2.595,1.125 2.595,1.375 2.575,1.375 ; 2.575,1.625 2.595,1.625 2.595,1.875 2.575,1.875 ; -2.575,-2.575 -2.575,2.575 2.575,2.575 2.575,-2.575 -2.575,-2.575
15 - Top Courtyards:
  lines w0.127: -3.1,-3.1 -3.1,3.1 3.1,3.1 3.1,-3.1 -3.1,-3.1
3D body "QFN50P500X500X100-33N.STEP": height 1, standoff 0, extent -2.595,-2.595 2.595,2.595

## QFP50P1600X1600X100-100N [mm] "TQFP-100, Thin QFP, 100-Leads, Body 14x14x1mm, Pitch 0.5mm, IPC Medium Density"
height 1
pads (100):
  oval 1.8x0.3 smd: 1(-7.55,6) 2(-7.55,5.5) 3(-7.55,5) 4(-7.55,4.5) 5(-7.55,4) 6(-7.55,3.5) 7(-7.55,3) 8(-7.55,2.5) 9(-7.55,2) 10(-7.55,1.5) 11(-7.55,1) 12(-7.55,0.5) 13(-7.55,0) 14(-7.55,-0.5) 15(-7.55,-1) 16(-7.55,-1.5) 17(-7.55,-2) 18(-7.55,-2.5) 19(-7.55,-3) 20(-7.55,-3.5) 21(-7.55,-4) 22(-7.55,-4.5) 23(-7.55,-5) 24(-7.55,-5.5) 25(-7.55,-6) 51(7.55,-6) 52(7.55,-5.5) 53(7.55,-5) 54(7.55,-4.5) 55(7.55,-4) 56(7.55,-3.5) 57(7.55,-3) 58(7.55,-2.5) 59(7.55,-2) 60(7.55,-1.5) 61(7.55,-1) 62(7.55,-0.5) 63(7.55,0) 64(7.55,0.5) 65(7.55,1) 66(7.55,1.5) 67(7.55,2) 68(7.55,2.5) 69(7.55,3) 70(7.55,3.5) 71(7.55,4) 72(7.55,4.5) 73(7.55,5) 74(7.55,5.5) 75(7.55,6)
  oval 0.3x1.8 smd: 26(-6,-7.55) 27(-5.5,-7.55) 28(-5,-7.55) 29(-4.5,-7.55) 30(-4,-7.55) 31(-3.5,-7.55) 32(-3,-7.55) 33(-2.5,-7.55) 34(-2,-7.55) 35(-1.5,-7.55) 36(-1,-7.55) 37(-0.5,-7.55) 38(0,-7.55) 39(0.5,-7.55) 40(1,-7.55) 41(1.5,-7.55) 42(2,-7.55) 43(2.5,-7.55) 44(3,-7.55) 45(3.5,-7.55) 46(4,-7.55) 47(4.5,-7.55) 48(5,-7.55) 49(5.5,-7.55) 50(6,-7.55) 76(6,7.55) 77(5.5,7.55) 78(5,7.55) 79(4.5,7.55) 80(4,7.55) 81(3.5,7.55) 82(3,7.55) 83(2.5,7.55) 84(2,7.55) 85(1.5,7.55) 86(1,7.55) 87(0.5,7.55) 88(0,7.55) 89(-0.5,7.55) 90(-1,7.55) 91(-1.5,7.55) 92(-2,7.55) 93(-2.5,7.55) 94(-3,7.55) 95(-3.5,7.55) 96(-4,7.55) 97(-4.5,7.55) 98(-5,7.55) 99(-5.5,7.55) 100(-6,7.55)
Top Overlay:
  region: -6.25,6.25 -4.75,6.25 -6.25,4.75
  lines w0.2: -6.25,-6.25 -6.25,6.25 6.25,6.25 6.25,-6.25 -6.25,-6.25
  text "." at -7.55,6.6 h0.05
13 - 3D Top Side:
  circle w0.1: c-6.1,6.1 r0.5
  lines w0.1: -7,-7 -7,7 7,7 7,-7 -7,-7
15 - Top Courtyards:
  lines w0.1: -0.5,0 0.5,0 ; 0,-0.5 0,0.5 ; -8.7,-8.7 -8.7,8.7 8.7,8.7 8.7,-8.7 -8.7,-8.7
3D body: height 1, standoff 0, extent -7,-7 7,7

## Relay_TE_IM-Series_Gull [mm] "TE Connectivity IM48DGR latching relay, gullwing SMD"
height 5.65
pads (9):
  round 1.27 on Mech15: 0(0,0)
  rrect20% 0.7x2 smd: 1(-3.8,-3) 2(-0.6,-3) 3(1.6,-3) 4(3.8,-3) 5(3.8,3) 6(1.6,3) 7(-0.6,3) 8(-3.8,3)
Top Overlay:
  lines w0.127: -4.1,0.5 -4.1,-0.5 -3.5,-0.5 ; -3.8,-1.73 -3.8,-1.3 ; -3.8,1.3 -3.8,1.7 ; 1.6,-0.762 0.838,0 1.6,0.762 ; 1.6,-0.762 1.6,0.762 ; 1.6,-0.762 2.362,0 1.6,0.762 ; -5.2,-4.3 -5.2,4.3 5.2,4.3 5.2,-4.3 -5.2,-4.3 ; -4.308,-1.3 -3.292,-1.3 -3.292,1.3 -4.308,1.3 -4.308,-1.3
  lines w0.381: -5.2,-2.045 -5.2,2.045
  text "S" at -3,-1.8 h1.2
  text "R" at -3,0.7 h1.2
  text "NC" at -1.6,-0.6 h1.2
  text "NO" at 2.7,-0.6 h1.2
13 - 3D Top Side:
  lines w0.127: -4,-3.04 -4,-3.755 -3.6,-3.755 -3.6,-3.04 ; -4,3.04 -4,3.755 -3.6,3.755 -3.6,3.04 ; -0.8,-3.04 -0.8,-3.755 -0.4,-3.755 -0.4,-3.04 ; -0.8,3.04 -0.8,3.755 -0.4,3.755 -0.4,3.04 ; 1.4,-3.04 1.4,-3.755 1.8,-3.755 1.8,-3.04 ; 1.4,3.04 1.4,3.755 1.8,3.755 1.8,3.04 ; 2.04,-3.04 2.04,-2.24 cw(c3.04,-2.24) 3.04,-1.24 5.04,-1.24 ; 3.6,-3.04 3.6,-3.755 4,-3.755 4,-3.04 ; 3.6,3.04 3.6,3.755 4,3.755 4,3.04 ; -5.04,-2.74 ccw(c-4.74,-2.74) -4.74,-3.04 4.74,-3.04 ccw(c4.74,-2.74) 5.04,-2.74 5.04,2.74 ccw(c4.74,2.74) 4.74,3.04 -4.74,3.04 ccw(c-4.74,2.74) -5.04,2.74 -5.04,-2.74 ; -4.54,-2.5 -4.04,-2.5 -4.04,2.5 -4.54,2.5 -4.54,-2.5
15 - Top Courtyards:
  lines w0.076: -5.07,-3 -2.53,-3 ; -3.8,-4.27 -3.8,-1.73
  lines w0.127: -5.3,-4.27 5.3,-4.27 5.3,4.3 -5.3,4.3 -5.3,-4.27
3D body "RELAY TE IM Series gull wing.STEP": height 5.65, standoff 0, extent -5.04,-3.755 5.04,3.755

## RESC1005X40N [mm] "Chip Resistor, Body 1.0x0.5mm, EIA 0402, IPC Medium Density"
height 0.4
pads (3):
  round 0.2 on Mech15: 0(0,0)
  rrect20% 0.6x0.6 smd: 1(-0.5,0) 2(0.5,0)
Top Layer:
  pour cut-out: -0.325,0.375 -0.2,0.5 0.2,0.5 0.325,0.375 0.325,-0.375 0.2,-0.5 -0.2,-0.5 -0.325,-0.375
Top Overlay:
  lines w0.127: -1.05,-0.55 1.05,-0.55 1.05,0.55 -1.05,0.55 -1.05,-0.55
08 - Top ASM Des:
  text ".Designator" at -0.925,-0.25 h0.8
13 - 3D Top Side:
  lines w0.05: 0.225,-0.274 -0.225,-0.274 0.225,-0.274 ; -0.525,-0.275 -0.225,-0.275 -0.225,0.275 -0.525,0.275 -0.525,-0.275 ; -0.225,0.274 0.225,0.274 -0.225,0.274 ; 0.225,-0.275 0.225,0.275 0.525,0.275 0.525,-0.275 0.225,-0.275
15 - Top Courtyards:
  lines w0.1: -1.05,-0.55 1.05,-0.55 1.05,0.55 -1.05,0.55 -1.05,-0.55
3D body "RES 0402 (1005 metric).STEP": height 0.4, standoff 0, extent -0.525,-0.275 0.525,0.275

## RESC1608N_ZERO [mm] "Chip Resistor, Body 1.6x0.8mm, 0603, IPC Medium Density"
height 0.55
pads (3):
  round 0.254 on Mech15: 0(0,0)
  rrect25% 0.9x1 smd: 1(-0.85,0) 2(0.85,0)
Top Layer:
  pour cut-out: -0.6,0.5 -0.4,0.7 0.4,0.7 0.6,0.5 0.6,-0.5 0.4,-0.7 -0.4,-0.7 -0.6,-0.5
Top Overlay:
  lines w0.1: -1.5,-0.7 -1.5,0.7 1.5,0.7 1.5,-0.7 -1.5,-0.7
08 - Top ASM Des:
  text ".Designator" at -1.3,-0.225 h0.8
13 - 3D Top Side:
  lines w0.05: -0.875,-0.475 -0.475,-0.475 -0.475,0.475 -0.875,0.475 -0.875,-0.475 ; -0.475,-0.474 0.475,-0.474 -0.475,-0.474 ; -0.475,0.474 0.475,0.474 -0.475,0.474 ; 0.475,-0.475 0.475,0.475 0.875,0.475 0.875,-0.475 0.475,-0.475
15 - Top Courtyards:
  lines w0.1: -1.5,-0.7 1.5,-0.7 1.5,0.7 -1.5,0.7 -1.5,-0.7
3D body "RES 0603 (1608 metric).STEP": height 0.54, standoff -0.01, extent -0.875,-0.475 0.875,0.475

## RESC1608X55N [mm] "Chip Resistor, Body 1.6x0.8mm, EIA 0603, IPC Medium Density"
height 0.55
pads (3):
  round 0.254 on Mech15: 0(0,0)
  rrect25% 0.9x1 smd: 1(-0.85,0) 2(0.85,0)
Top Layer:
  pour cut-out: -0.6,0.5 -0.4,0.7 0.4,0.7 0.6,0.5 0.6,-0.5 0.4,-0.7 -0.4,-0.7 -0.6,-0.5
Top Overlay:
  lines w0.1: -1.5,-0.7 -1.5,0.7 1.5,0.7 1.5,-0.7 -1.5,-0.7
08 - Top ASM Des:
  text ".Designator" at -1.275,-0.325 h1
13 - 3D Top Side:
  lines w0.05: -0.875,-0.475 -0.875,0.475 -0.475,0.475 -0.475,-0.475 -0.875,-0.475 ; -0.475,-0.474 0.475,-0.474 -0.475,-0.474 ; -0.475,0.474 0.475,0.474 -0.475,0.474 ; 0.475,-0.475 0.875,-0.475 0.875,0.475 0.475,0.475 0.475,-0.475
15 - Top Courtyards:
  lines w0.1: -1.5,-0.7 1.5,-0.7 1.5,0.7 -1.5,0.7 -1.5,-0.7
3D body "RES 0603 (1608 metric).STEP": height 0.54, standoff -0.01, extent -0.875,-0.475 0.875,0.475

## RESC2012N_ZERO [mm] "Chip Resistor, Body 2.0x1.2mm, 0805, IPC Medium Density"
height 0.7
pads (3):
  round 0.254 on Mech15: 0(0,0)
  rrect25% 0.8x1.3 smd: 1(-1,0) 2(1,0)
Top Layer:
  pour cut-out: -0.725,0.65 -0.525,0.85 0.525,0.85 0.725,0.65 0.725,-0.65 0.525,-0.85 -0.525,-0.85 -0.725,-0.65
Top Overlay:
  lines w0.1: -1.6,-0.85 1.6,-0.85 1.6,0.85 -1.6,0.85 -1.6,-0.85
08 - Top ASM Des:
  text ".Designator" at -1.375,-0.275 h1
13 - 3D Top Side:
  lines w0.05: 0.6,-0.674 -0.6,-0.674 ; -0.6,-0.674 0.6,-0.674 ; -0.6,-0.675 -1.1,-0.675 -1.1,0.675 -0.6,0.675 -0.6,-0.675 ; 0.6,-0.675 1.1,-0.675 1.1,0.675 0.6,0.675 ; 0.6,-0.675 0.6,0.675 ; 0.6,0.674 -0.6,0.674 0.6,0.674
15 - Top Courtyards:
  lines w0.1: -1.6,-0.85 -1.6,0.85 1.6,0.85 1.6,-0.85 -1.6,-0.85
3D body "RES 0805 (2012 metric).STEP": height 0.69, standoff -0.01, extent -1.1,-0.675 1.1,0.675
